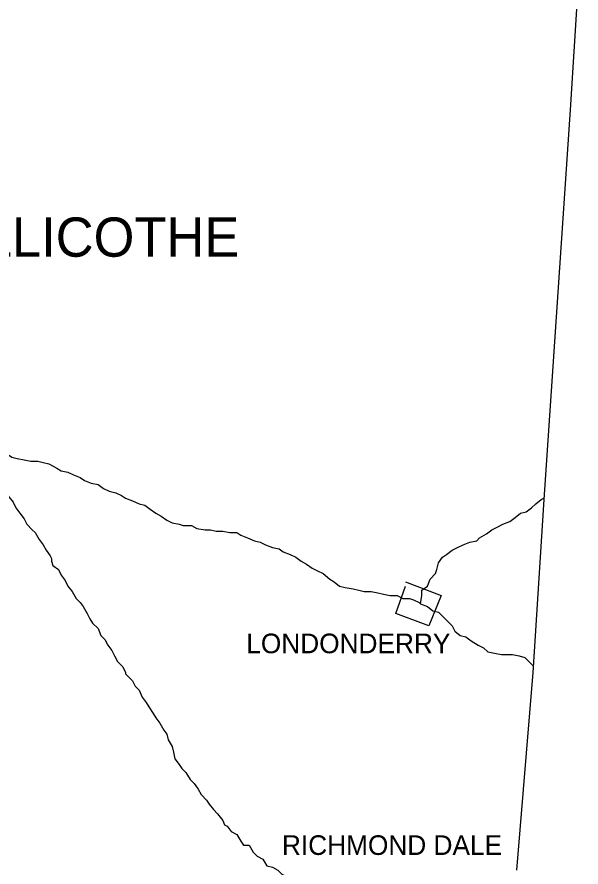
# Model space of a CAD drawing. Extents: x 0 to 34, y 0 to 22.
# Drawn here: x 6.387 to 6.947, y 18.506 to 19.351 of the extents above; entities that cross this region are included whole.
import ezdxf

# ---------------------------------------------------------------- set-up
doc = ezdxf.new("R2010")
doc.units = 0
doc.layers.add('Default', color=7, linetype='Continuous')

msp = doc.modelspace()

# ---------------------------------------------------------------- linework, layer by layer
at = {"layer": 'Default'}
for points in [[(6.94709, 19.42727), (6.93619, 19.25821), (6.91028, 18.871), (6.89937, 18.6992), (6.88301, 18.50287)], [(6.36355, 18.91871), (6.37037, 18.91871), (6.37718, 18.91599), (6.38127, 18.91326), (6.38673, 18.9119), (6.39354, 18.91053), (6.40036, 18.90917), (6.40718, 18.90917), (6.41263, 18.90781), (6.41809, 18.90644), (6.42627, 18.90235), (6.43036, 18.89963), (6.43717, 18.89826), (6.44263, 18.89554), (6.44944, 18.89281), (6.45354, 18.89008), (6.46035, 18.88736), (6.46717, 18.88599), (6.47262, 18.8819), (6.47808, 18.87918), (6.48489, 18.87781), (6.49035, 18.87509)], [(6.36764, 18.90235), (6.369, 18.89554), (6.369, 18.89008), (6.37173, 18.88327), (6.37582, 18.87918), (6.37855, 18.87372), (6.38264, 18.86827), (6.38536, 18.86281), (6.38945, 18.85736), (6.39354, 18.85191), (6.39627, 18.84645), (6.40173, 18.841), (6.40445, 18.83827), (6.40854, 18.83146), (6.41263, 18.826), (6.41536, 18.82055), (6.41945, 18.81509), (6.42081, 18.81237), (6.42081, 18.80964)], [(6.49035, 18.87509), (6.49444, 18.87236), (6.50125, 18.86963), (6.50807, 18.8669), (6.51353, 18.86554), (6.51898, 18.86145), (6.52443, 18.85736), (6.52989, 18.85463), (6.53534, 18.85054), (6.54079, 18.84782), (6.54761, 18.84645), (6.5517, 18.84509), (6.55988, 18.84509), (6.56534, 18.84236), (6.57352, 18.841), (6.57897, 18.841), (6.58442, 18.83964), (6.59124, 18.83964), (6.59806, 18.83827), (6.60487, 18.83827), (6.60897, 18.83555), (6.61578, 18.83282), (6.6226, 18.83009), (6.62805, 18.82873), (6.63351, 18.826), (6.64032, 18.82328), (6.64714, 18.82191), (6.65123, 18.81919), (6.65805, 18.81646), (6.6635, 18.81373), (6.66896, 18.80964), (6.67441, 18.80691), (6.67986, 18.80282), (6.68532, 18.8001), (6.69077, 18.79737), (6.69759, 18.79192), (6.70168, 18.78919), (6.70713, 18.7851), (6.71259, 18.78374), (6.72077, 18.78237), (6.72622, 18.78101), (6.73167, 18.77965), (6.73849, 18.77965), (6.74531, 18.77828), (6.75076, 18.77692), (6.75758, 18.77556), (6.7644, 18.77556), (6.76985, 18.77283), (6.77667, 18.77283), (6.78076, 18.77147), (6.78621, 18.76874), (6.78757, 18.76738)], [(6.78757, 18.76738), (6.78894, 18.77556), (6.78894, 18.78101), (6.79439, 18.7851), (6.79712, 18.79192), (6.80257, 18.79737), (6.80393, 18.80146), (6.8053, 18.80828), (6.80939, 18.81373), (6.81348, 18.81646), (6.81893, 18.82055), (6.82439, 18.82328), (6.82984, 18.826), (6.83666, 18.82873), (6.84347, 18.83009), (6.8462, 18.83282), (6.85302, 18.83691), (6.85847, 18.841), (6.86392, 18.84373), (6.86938, 18.84645), (6.8762, 18.84918), (6.88165, 18.85327), (6.8871, 18.85736), (6.89256, 18.85872), (6.89801, 18.86281), (6.9021, 18.8669), (6.90755, 18.871), (6.91028, 18.87236), (6.91028, 18.87236)], [(6.42081, 18.80964), (6.42218, 18.80555), (6.42763, 18.80146), (6.43036, 18.79601), (6.43445, 18.79055), (6.43717, 18.7851), (6.44126, 18.77965), (6.44535, 18.77283), (6.44944, 18.76874), (6.45217, 18.76465), (6.45626, 18.75783), (6.45899, 18.75238), (6.46172, 18.74829), (6.46717, 18.74283), (6.4699, 18.73602), (6.47399, 18.73193), (6.47671, 18.72647), (6.4808, 18.72102), (6.48353, 18.71557), (6.48626, 18.71011), (6.49171, 18.70466), (6.49444, 18.6992), (6.49444, 18.69784), (6.4958, 18.69648)], [(6.77258, 18.78919), (6.80802, 18.77556), (6.79575, 18.74556), (6.76303, 18.75783), (6.77258, 18.7851)], [(6.78757, 18.76738), (6.79439, 18.76465), (6.79984, 18.76056), (6.8053, 18.75919), (6.80939, 18.7551), (6.81348, 18.75101), (6.81893, 18.74556), (6.82166, 18.74011), (6.82711, 18.73602), (6.83257, 18.73465), (6.83802, 18.73056), (6.84484, 18.72647), (6.85029, 18.72375), (6.85438, 18.71966), (6.8612, 18.71829), (6.86802, 18.71693), (6.87347, 18.71693), (6.87892, 18.71693), (6.88574, 18.71557), (6.89119, 18.7142), (6.89528, 18.71011), (6.89937, 18.70602)], [(6.4958, 18.69648), (6.50125, 18.69102), (6.50398, 18.68557), (6.50807, 18.68148), (6.5108, 18.67466), (6.51489, 18.66921), (6.51762, 18.66512), (6.52171, 18.6583), (6.52443, 18.65421), (6.52852, 18.64876), (6.53261, 18.64194), (6.53534, 18.63785), (6.5367, 18.6324), (6.54079, 18.62558), (6.54216, 18.62013), (6.54352, 18.61331), (6.54761, 18.60786), (6.55034, 18.60376), (6.55443, 18.59967), (6.55852, 18.59286), (6.56261, 18.58877), (6.5667, 18.58331), (6.56943, 18.57786), (6.57488, 18.57241), (6.57761, 18.56832), (6.5817, 18.56286), (6.58579, 18.55877), (6.59124, 18.55195), (6.5926, 18.54786), (6.59533, 18.5465)], [(6.59533, 18.5465), (6.59942, 18.54105), (6.60487, 18.53832), (6.60897, 18.5315), (6.61169, 18.52741), (6.61715, 18.52741), (6.62124, 18.5206), (6.62533, 18.51651), (6.63078, 18.51378), (6.63487, 18.50696), (6.64032, 18.5056), (6.64578, 18.50287), (6.64987, 18.49878), (6.65532, 18.49605), (6.66214, 18.49333), (6.66623, 18.4906), (6.67305, 18.48924), (6.67714, 18.48378), (6.67714, 18.48242)]]:
    msp.add_lwpolyline(points, dxfattribs=at)

# ---------------------------------------------------------------- texts
for s, height, p in [('CHILLICOTHE', 0.0390047, (6.26266, 19.11232)), ('LONDONDERRY', 0.0195024, (6.61442, 18.71829)), ('RICHMOND DALE', 0.0195024, (6.64987, 18.51787))]:
    msp.add_text(s, height=height, dxfattribs=at).set_placement(p)

doc.saveas('drawing.dxf')
